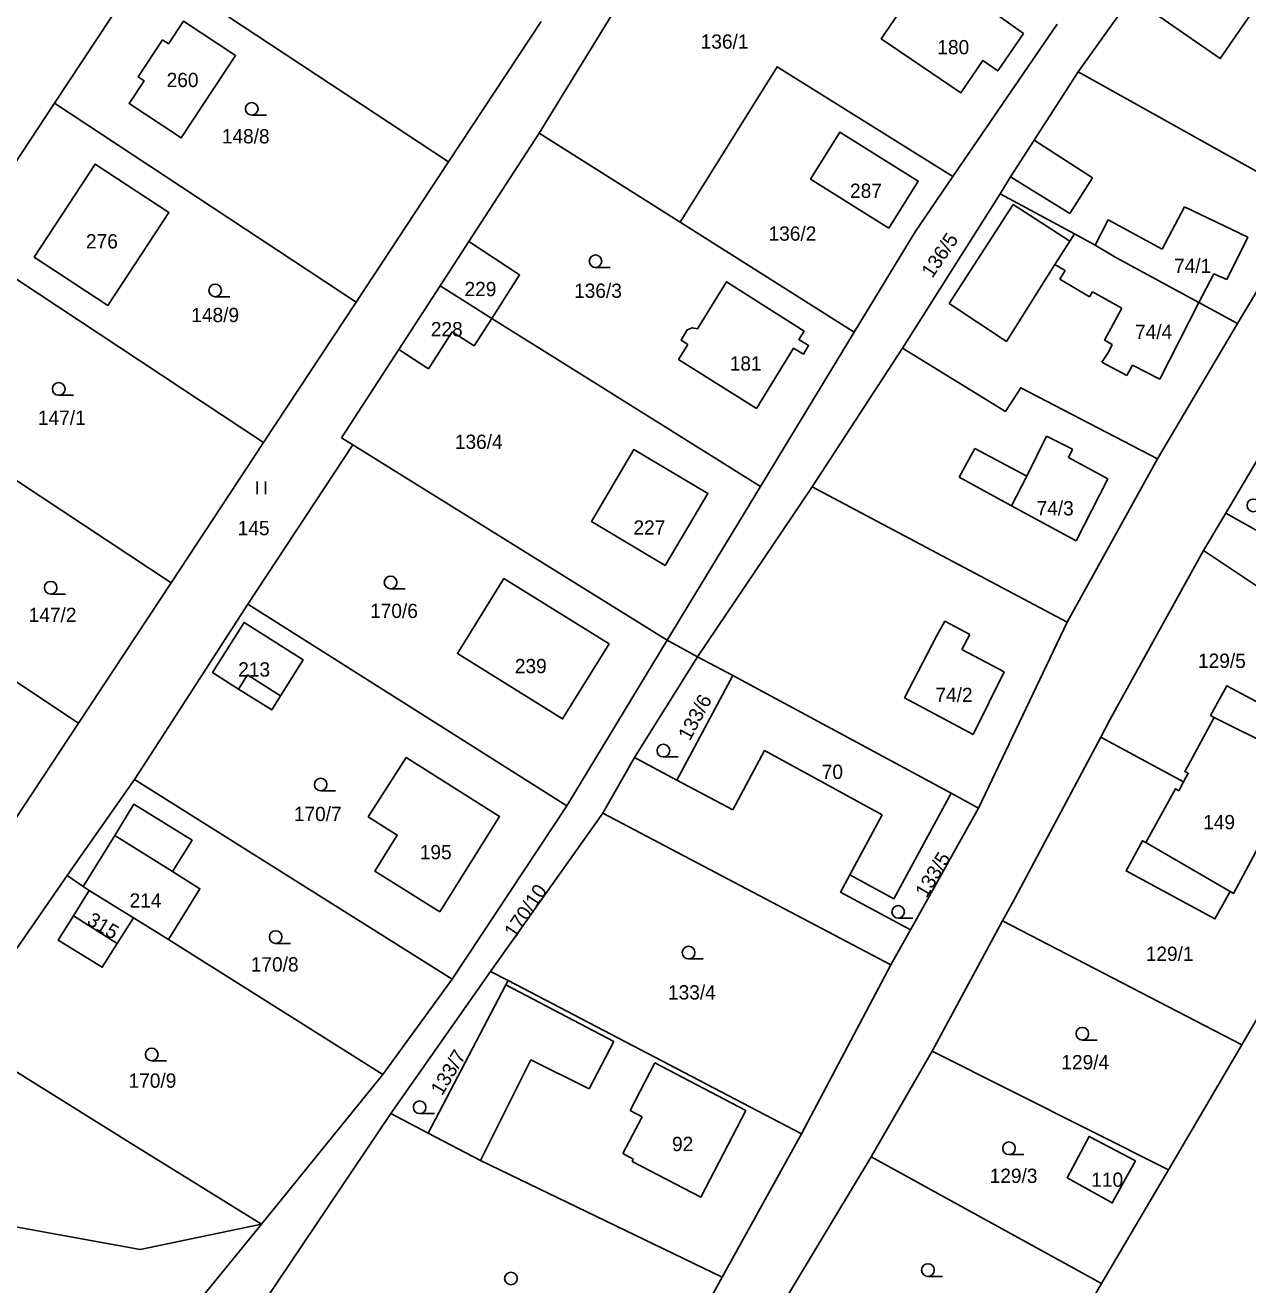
# Model space of a CAD drawing. Extents: x -7483133 to -743907, y -11317770 to -1129777.
# Drawn here: x -746482.5 to -746337, y -1131945.9 to -1131796 of the extents above; entities that cross this region are included whole.
import ezdxf

# ---------------------------------------------------------------- set-up
doc = ezdxf.new("R2010")
doc.units = 0
for name, color, linetype in [('Hranice parcel', 7, 'Continuous'), ('Parcelní čísla', 7, 'Continuous'), ('Vnitřní kresba', 7, 'Continuous'), ('Značky kultur', 7, 'Continuous')]:
    doc.layers.add(name, color=color, linetype=linetype)

msp = doc.modelspace()

# ---------------------------------------------------------------- linework, layer by layer
at = {"layer": 'Hranice parcel'}
for p, q in [((-746343.18, -1131781.93), (-746357.15, -1131801.57)), ((-746478.99, -1131805.28), (-746467.98, -1131788.59)), ((-746467.98, -1131788.59), (-746432.08, -1131812.26)), ((-746421.07, -1131795.57), (-746432.08, -1131812.26)), ((-746372.05, -1131814.02), (-746359.64, -1131795.9)), ((-746329.51, -1131817), (-746357.15, -1131801.57)), ((-746490, -1131821.98), (-746478.99, -1131805.28)), ((-746478.99, -1131805.28), (-746443.09, -1131828.96)), ((-746421.32, -1131808.85), (-746429.68, -1131821.74)), ((-746421.32, -1131808.85), (-746404.51, -1131819.44)), ((-746432.08, -1131812.26), (-746443.09, -1131828.96)), ((-746366.45, -1131816.06), (-746378.06, -1131834.44)), ((-746338.17, -1131831.49), (-746329.51, -1131817)), ((-746404.51, -1131819.44), (-746383.82, -1131832.55)), ((-746429.68, -1131821.74), (-746433.1, -1131827.02)), ((-746454.1, -1131845.66), (-746490, -1131821.98)), ((-746438.01, -1131834.6), (-746433.1, -1131827.02)), ((-746433.1, -1131827.02), (-746426.94, -1131830.89)), ((-746443.09, -1131828.96), (-746454.1, -1131845.66)), ((-746426.94, -1131830.89), (-746429.05, -1131834.18)), ((-746347.69, -1131847.59), (-746338.17, -1131831.49)), ((-746394.96, -1131850.9), (-746383.82, -1131832.55)), ((-746438.01, -1131834.6), (-746444.83, -1131845.11)), ((-746434.48, -1131836.9), (-746438.01, -1131834.6)), ((-746378.06, -1131834.44), (-746388.82, -1131850.94)), ((-746501.01, -1131838.68), (-746465.11, -1131862.35)), ((-746332.13, -1131841.46), (-746339.57, -1131854.09)), ((-746454.1, -1131845.66), (-746465.11, -1131862.35)), ((-746444.83, -1131845.11), (-746443.47, -1131845.95)), ((-746443.47, -1131845.95), (-746455.99, -1131864.91)), ((-746358.44, -1131867.04), (-746347.69, -1131847.59)), ((-746406.07, -1131869.18), (-746394.96, -1131850.9)), ((-746388.82, -1131850.94), (-746402.47, -1131871.17)), ((-746358.44, -1131867.04), (-746388.82, -1131850.94)), ((-746339.57, -1131854.09), (-746342.22, -1131858.51)), ((-746334.77, -1131856.76), (-746339.57, -1131854.09)), ((-746512.02, -1131855.37), (-746476.13, -1131879.05)), ((-746342.22, -1131858.51), (-746319.24, -1131873.86)), ((-746465.11, -1131862.35), (-746476.13, -1131879.05)), ((-746455.99, -1131864.91), (-746418.01, -1131888.89)), ((-746369.01, -1131889.16), (-746358.44, -1131867.04)), ((-746406.07, -1131869.18), (-746418.01, -1131888.89)), ((-746402.47, -1131871.17), (-746406.07, -1131869.18)), ((-746409.94, -1131883.15), (-746402.47, -1131871.17)), ((-746402.47, -1131871.17), (-746398.27, -1131873.41)), ((-746398.27, -1131873.41), (-746404.9, -1131885.84)), ((-746372.28, -1131887.39), (-746398.27, -1131873.41)), ((-746476.13, -1131879.05), (-746487.14, -1131895.74)), ((-746413.73, -1131889.78), (-746409.94, -1131883.15)), ((-746404.9, -1131885.84), (-746409.94, -1131883.15)), ((-746469.48, -1131885.78), (-746477.5, -1131897.18)), ((-746469.48, -1131885.78), (-746431.68, -1131909.51)), ((-746372.28, -1131887.39), (-746369.01, -1131889.16)), ((-746418.01, -1131888.89), (-746431.68, -1131909.51)), ((-746377.12, -1131903.66), (-746369.01, -1131889.16)), ((-746427.09, -1131908.61), (-746413.73, -1131889.78)), ((-746413.73, -1131889.78), (-746379.44, -1131907.81)), ((-746475.58, -1131898.52), (-746477.5, -1131897.18)), ((-746474.85, -1131898.97), (-746475.58, -1131898.52)), ((-746474.85, -1131898.97), (-746469.61, -1131902.21)), ((-746377.12, -1131903.66), (-746385.43, -1131899.17)), ((-746465.42, -1131904.8), (-746469.61, -1131902.21)), ((-746366.14, -1131902.59), (-746374.51, -1131918.11)), ((-746366.14, -1131902.59), (-746337.68, -1131917.35)), ((-746379.44, -1131907.81), (-746377.12, -1131903.66)), ((-746439.92, -1131920.87), (-746465.42, -1131904.8)), ((-746438.95, -1131925.52), (-746427.09, -1131908.61)), ((-746427.09, -1131908.61), (-746425.01, -1131909.7)), ((-746390.09, -1131927.94), (-746379.44, -1131907.81)), ((-746431.68, -1131909.51), (-746439.92, -1131920.87)), ((-746390.09, -1131927.94), (-746425.01, -1131909.7)), ((-746337.68, -1131917.35), (-746346.4, -1131932.2)), ((-746374.51, -1131918.11), (-746381.8, -1131930.69)), ((-746346.4, -1131932.2), (-746374.51, -1131918.11)), ((-746454.36, -1131938.7), (-746439.92, -1131920.87)), ((-746453.89, -1131947.67), (-746438.95, -1131925.52)), ((-746434.5, -1131927.85), (-746438.95, -1131925.52)), ((-746434.5, -1131927.85), (-746428.29, -1131931.1)), ((-746399.53, -1131945), (-746390.09, -1131927.94)), ((-746428.29, -1131931.1), (-746399.53, -1131945)), ((-746381.8, -1131930.69), (-746395.75, -1131953.81)), ((-746354.37, -1131945.76), (-746381.8, -1131930.69)), ((-746346.4, -1131932.2), (-746354.37, -1131945.76)), ((-746461.71, -1131947.7), (-746454.36, -1131938.7)), ((-746408.25, -1131960.77), (-746399.53, -1131945)), ((-746354.37, -1131945.76), (-746356.8, -1131949.89))]:
    msp.add_line(p, q, dxfattribs=at)
for points in [[(-746397.28, -1131770.07), (-746409.98, -1131790.4), (-746421.32, -1131808.85)], [(-746363.67, -1131796.98), (-746374.76, -1131789.08), (-746380.59, -1131797.61), (-746371.1, -1131804.04), (-746368.51, -1131800.22), (-746366.72, -1131801.44), (-746363.67, -1131796.98)], [(-746466.13, -1131797.76), (-746465.44, -1131798.22), (-746463.66, -1131795.54), (-746457.45, -1131799.62), (-746463.9, -1131809.41), (-746470.12, -1131805.34), (-746468.34, -1131802.64), (-746469.02, -1131802.17), (-746466.13, -1131797.76)], [(-746372.05, -1131814.02), (-746392.96, -1131800.95), (-746404.51, -1131819.44)], [(-746357.15, -1131801.57), (-746362.37, -1131809.67), (-746365.19, -1131814.06), (-746366.45, -1131816.06)], [(-746379.7, -1131820.14), (-746389, -1131814.31), (-746385.5, -1131808.73), (-746376.19, -1131814.56), (-746379.7, -1131820.14)], [(-746481.4, -1131823.61), (-746474.14, -1131812.54), (-746465.37, -1131818.3), (-746472.64, -1131829.35), (-746481.4, -1131823.61)], [(-746383.82, -1131832.55), (-746376.54, -1131820.58), (-746372.05, -1131814.02)], [(-746366.45, -1131816.06), (-746357.6, -1131820.84), (-746355.14, -1131822.17), (-746352.66, -1131823.64), (-746342.8, -1131829.01), (-746338.17, -1131831.49)], [(-746429.68, -1131821.74), (-746423.64, -1131825.73), (-746426.94, -1131830.89)], [(-746389.76, -1131832.4), (-746399, -1131826.54), (-746402.44, -1131832.12)], [(-746426.94, -1131830.89), (-746415.96, -1131837.77), (-746394.96, -1131850.9)], [(-746402.44, -1131832.12), (-746403.09, -1131832), (-746403.68, -1131832.25), (-746404.4, -1131833.49), (-746403.6, -1131833.99)], [(-746395.45, -1131841.62), (-746391.02, -1131834.44), (-746389.86, -1131835.15), (-746389.23, -1131834.12), (-746390.38, -1131833.41), (-746389.76, -1131832.4)], [(-746429.05, -1131834.18), (-746431.65, -1131832.5), (-746434.48, -1131836.9)], [(-746403.6, -1131833.99), (-746404.71, -1131835.79), (-746395.45, -1131841.62)], [(-746347.69, -1131847.59), (-746363.99, -1131839.14), (-746365.8, -1131841.96), (-746378.06, -1131834.44)], [(-746443.47, -1131845.95), (-746427.32, -1131855.97), (-746406.07, -1131869.18)], [(-746406.32, -1131860.29), (-746401.23, -1131851.72), (-746410.03, -1131846.49), (-746415.09, -1131855.08), (-746406.32, -1131860.29)], [(-746354.46, -1131880.72), (-746353.37, -1131878.68), (-746342.22, -1131858.51)], [(-746412.97, -1131869.62), (-746425.5, -1131861.83), (-746431.03, -1131870.79), (-746418.52, -1131878.56), (-746412.97, -1131869.62)], [(-746455.99, -1131864.91), (-746466.63, -1131881.37), (-746469.48, -1131885.78)], [(-746452.09, -1131875.82), (-746449.39, -1131871.54), (-746456.41, -1131867.08), (-746460.17, -1131873.04), (-746457.09, -1131875.01), (-746453.14, -1131877.48), (-746452.09, -1131875.82)], [(-746333.74, -1131890.21), (-746330.25, -1131883.74), (-746330.66, -1131883.52), (-746328.89, -1131880.25), (-746339.47, -1131874.63), (-746341.38, -1131878.14), (-746340.94, -1131878.38), (-746343.79, -1131883.58), (-746344.46, -1131884.81), (-746344.04, -1131885.02), (-746344.6, -1131886.06)], [(-746354.46, -1131880.72), (-746364.94, -1131900.36), (-746366.14, -1131902.59)], [(-746344.6, -1131886.06), (-746346.67, -1131884.94), (-746354.46, -1131880.72)], [(-746433.13, -1131901.53), (-746426.01, -1131890.18), (-746437.12, -1131883.14), (-746441.65, -1131890.22)], [(-746344.6, -1131886.06), (-746345.17, -1131887.1), (-746345.57, -1131886.87), (-746346.84, -1131889.17), (-746349.1, -1131893.27), (-746349.5, -1131893.05), (-746351.45, -1131896.64), (-746340.87, -1131902.35), (-746339.07, -1131899.09), (-746338.66, -1131899.32), (-746335.16, -1131892.84)], [(-746385.43, -1131899.17), (-746384.32, -1131897.11), (-746379.07, -1131899.95), (-746372.28, -1131887.39)], [(-746465.42, -1131904.8), (-746461.69, -1131898.76), (-746464.95, -1131896.72), (-746462.62, -1131892.99), (-746469.56, -1131888.71), (-746471.81, -1131892.44), (-746475.58, -1131898.52)], [(-746441.65, -1131890.22), (-746438.2, -1131892.39), (-746440.88, -1131896.67), (-746433.13, -1131901.53)], [(-746454.36, -1131938.7), (-746469.66, -1131929.19), (-746490.63, -1131916.16), (-746477.5, -1131897.18)], [(-746469.61, -1131902.21), (-746471.53, -1131905.27), (-746473.31, -1131908.12), (-746478.56, -1131904.89), (-746476.75, -1131902), (-746474.85, -1131898.97)], [(-746545.06, -1131905.46), (-746551.21, -1131914.79), (-746552.36, -1131918.38), (-746542.1, -1131920.25), (-746542.46, -1131922.22), (-746512.94, -1131927.58), (-746514.01, -1131933.49), (-746468.81, -1131941.71), (-746454.36, -1131938.7)], [(-746331.51, -1131906.85), (-746336.79, -1131915.84), (-746337.68, -1131917.35)], [(-746425.01, -1131909.7), (-746425.29, -1131910.22), (-746434.5, -1131927.85)], [(-746350.32, -1131931.16), (-746355.85, -1131928.24), (-746358.46, -1131933.16), (-746353.09, -1131936.15), (-746350.32, -1131931.16)]]:
    msp.add_lwpolyline(points, dxfattribs=at)
at = {"layer": 'Vnitřní kresba'}
for p, q in [((-746355.46, -1131814.18), (-746362.37, -1131809.67)), ((-746365.19, -1131814.06), (-746358.15, -1131818.41)), ((-746358.15, -1131818.41), (-746355.46, -1131814.18)), ((-746364.87, -1131817.35), (-746372.49, -1131829.12)), ((-746364.87, -1131817.35), (-746358.14, -1131821.7)), ((-746344.47, -1131817.61), (-746347.15, -1131822.64)), ((-746336.96, -1131821.23), (-746344.47, -1131817.61)), ((-746353.59, -1131819.15), (-746355.14, -1131822.17)), ((-746347.15, -1131822.64), (-746353.59, -1131819.15)), ((-746358.14, -1131821.7), (-746359.91, -1131824.5)), ((-746358.14, -1131821.7), (-746357.6, -1131820.84)), ((-746339.44, -1131826.26), (-746336.96, -1131821.23)), ((-746359.91, -1131824.5), (-746365.69, -1131833.66)), ((-746358.68, -1131825.18), (-746359.91, -1131824.5)), ((-746359.31, -1131826.21), (-746358.68, -1131825.18)), ((-746355.81, -1131828.32), (-746359.31, -1131826.21)), ((-746342.8, -1131829.01), (-746340.98, -1131825.59)), ((-746340.98, -1131825.59), (-746339.44, -1131826.26)), ((-746355.43, -1131827.75), (-746355.81, -1131828.32)), ((-746351.94, -1131829.66), (-746355.43, -1131827.75)), ((-746372.49, -1131829.12), (-746365.69, -1131833.66)), ((-746342.8, -1131829.01), (-746347.43, -1131838.14)), ((-746354.01, -1131833.47), (-746351.94, -1131829.66)), ((-746353.11, -1131834.02), (-746354.01, -1131833.47)), ((-746354.32, -1131836.11), (-746353.54, -1131834.9)), ((-746353.54, -1131834.9), (-746353.11, -1131834.02)), ((-746351.37, -1131837.7), (-746354.32, -1131836.11)), ((-746350.68, -1131836.47), (-746351.37, -1131837.7)), ((-746347.43, -1131838.14), (-746350.68, -1131836.47)), ((-746363.27, -1131849.66), (-746360.93, -1131844.9)), ((-746360.93, -1131844.9), (-746357.84, -1131846.44)), ((-746371.32, -1131849.8), (-746369.44, -1131846.38)), ((-746369.44, -1131846.38), (-746363.27, -1131849.66)), ((-746357.84, -1131846.44), (-746358.31, -1131847.45)), ((-746358.31, -1131847.45), (-746353.62, -1131850)), ((-746365.09, -1131853.19), (-746371.32, -1131849.8)), ((-746363.27, -1131849.66), (-746365.09, -1131853.19)), ((-746353.62, -1131850), (-746357.37, -1131857.38)), ((-746357.37, -1131857.38), (-746365.09, -1131853.19)), ((-746374.01, -1131868.72), (-746373, -1131866.91)), ((-746373, -1131866.91), (-746370.05, -1131868.52)), ((-746377.83, -1131876.03), (-746374.01, -1131868.72)), ((-746370.05, -1131868.52), (-746370.98, -1131870.31)), ((-746370.98, -1131870.31), (-746365.95, -1131872.95)), ((-746456.02, -1131873.33), (-746457.09, -1131875.01)), ((-746452.09, -1131875.82), (-746456.02, -1131873.33)), ((-746365.95, -1131872.95), (-746369.63, -1131880.4)), ((-746369.63, -1131880.4), (-746377.83, -1131876.03)), ((-746330.66, -1131883.52), (-746340.94, -1131878.38)), ((-746394.49, -1131882.3), (-746398.26, -1131889.38)), ((-746380.47, -1131889.98), (-746394.49, -1131882.3)), ((-746398.26, -1131889.38), (-746404.9, -1131885.84)), ((-746384.32, -1131897.11), (-746380.47, -1131889.98)), ((-746464.95, -1131896.72), (-746471.81, -1131892.44)), ((-746339.07, -1131899.09), (-746349.1, -1131893.27)), ((-746476.75, -1131902), (-746471.53, -1131905.27)), ((-746412.42, -1131916.94), (-746425.29, -1131910.22)), ((-746412.42, -1131916.94), (-746415.37, -1131922.58)), ((-746428.29, -1131931.1), (-746422.28, -1131919.11)), ((-746422.28, -1131919.11), (-746415.37, -1131922.58)), ((-746407.53, -1131919.5), (-746410.48, -1131925.14)), ((-746396.69, -1131925.16), (-746407.53, -1131919.5)), ((-746410.48, -1131925.14), (-746409.03, -1131925.9)), ((-746396.69, -1131925.16), (-746402.08, -1131935.48)), ((-746409.03, -1131925.9), (-746411.35, -1131930.29)), ((-746411.35, -1131930.29), (-746410.1, -1131930.95)), ((-746410.1, -1131930.95), (-746410.24, -1131931.22)), ((-746410.24, -1131931.22), (-746402.08, -1131935.48))]:
    msp.add_line(p, q, dxfattribs=at)
msp.add_lwpolyline([(-746333.21, -1131789.79), (-746340.23, -1131799.97), (-746348.05, -1131794.58), (-746341.05, -1131784.42), (-746333.21, -1131789.79)], dxfattribs=at)
at = {"layer": 'Značky kultur'}
for p, q in [((-746455.52, -1131806.71), (-746453.77, -1131806.71)), ((-746414.6, -1131824.84), (-746412.85, -1131824.84)), ((-746459.87, -1131828.32), (-746458.12, -1131828.32)), ((-746478.49, -1131840.04), (-746476.74, -1131840.04)), ((-746454.88, -1131851.82), (-746454.88, -1131850.32)), ((-746453.88, -1131851.82), (-746453.88, -1131850.32)), ((-746479.45, -1131863.7), (-746477.7, -1131863.7)), ((-746438.99, -1131863.07), (-746437.24, -1131863.07)), ((-746406.52, -1131883.08), (-746404.77, -1131883.08)), ((-746447.31, -1131887.11), (-746445.56, -1131887.11)), ((-746378.57, -1131902.27), (-746376.82, -1131902.27)), ((-746452.67, -1131905.27), (-746450.92, -1131905.27)), ((-746403.52, -1131907.12), (-746401.77, -1131907.12)), ((-746356.65, -1131916.77), (-746354.9, -1131916.77)), ((-746467.42, -1131919.24), (-746465.67, -1131919.24)), ((-746435.53, -1131925.52), (-746433.78, -1131925.52)), ((-746365.38, -1131930.4), (-746363.63, -1131930.4)), ((-746375.03, -1131944.9), (-746373.28, -1131944.9))]:
    msp.add_line(p, q, dxfattribs=at)
for centre in [(-746455.52, -1131805.96), (-746414.6, -1131824.09), (-746459.87, -1131827.57), (-746478.49, -1131839.29), (-746336.3, -1131853.15), (-746479.45, -1131862.95), (-746438.99, -1131862.32), (-746406.52, -1131882.33), (-746447.31, -1131886.36), (-746378.57, -1131901.52), (-746452.67, -1131904.52), (-746403.52, -1131906.37), (-746356.65, -1131916.02), (-746467.42, -1131918.49), (-746435.53, -1131924.77), (-746365.38, -1131929.65), (-746424.67, -1131945.15), (-746375.03, -1131944.15)]:
    msp.add_circle(centre, 0.75, dxfattribs=at)

# ---------------------------------------------------------------- texts
at = {"layer": 'Parcelní čísla'}
for s, p in [('136/1', (-746402.08, -1131798.8)), ('180', (-746373.91, -1131799.47)), ('260', (-746465.65, -1131803.37)), ('148/8', (-746459.08, -1131810.07)), ('287', (-746384.3, -1131816.56)), ('136/2', (-746394, -1131821.65)), ('276', (-746475.25, -1131822.57)), ('74/1', (-746345.74, -1131825.5)), ('229', (-746430.19, -1131828.25)), ('136/3', (-746417.15, -1131828.45)), ('148/9', (-746462.71, -1131831.34)), ('228', (-746434.2, -1131833.03)), ('74/4', (-746350.38, -1131833.35)), ('181', (-746398.62, -1131837.11)), ('147/1', (-746480.97, -1131843.57)), ('136/4', (-746431.34, -1131846.43)), ('74/3', (-746362.1, -1131854.34)), ('227', (-746410.08, -1131856.63)), ('145', (-746457.19, -1131856.7)), ('147/2', (-746482.07, -1131867.03)), ('170/6', (-746441.43, -1131866.55)), ('239', (-746424.2, -1131873.12)), ('129/5', (-746342.88, -1131872.49)), ('213', (-746457.13, -1131873.52)), ('74/2', (-746374.14, -1131876.55)), ('70', (-746387.67, -1131885.7)), ('170/7', (-746450.51, -1131890.72)), ('149', (-746342.27, -1131891.69)), ('195', (-746435.51, -1131895.26)), ('214', (-746470.06, -1131901.02)), ('129/1', (-746349.1, -1131907.36)), ('170/8', (-746455.63, -1131908.62)), ('133/4', (-746405.97, -1131911.95)), ('129/4', (-746359.15, -1131920.26)), ('170/9', (-746470.18, -1131922.45)), ('92', (-746405.49, -1131929.99)), ('129/3', (-746367.68, -1131933.78)), ('110', (-746355.59, -1131934.24))]:
    msp.add_text(s, height=1.7, dxfattribs=at).set_placement(p)
for s, rotation, p in [('136/5', 56, (-746374.51, -1131826.2)), ('133/6', 62, (-746403.36, -1131881.26)), ('133/5', 59, (-746375.2, -1131899.96)), ('170/10', 56, (-746424.17, -1131904.75)), ('315', 329, (-746475.27, -1131902.92)), ('133/7', 59, (-746432.87, -1131923.49))]:
    msp.add_text(s, height=1.7, rotation=rotation, dxfattribs=at).set_placement(p)

doc.saveas('drawing.dxf')
